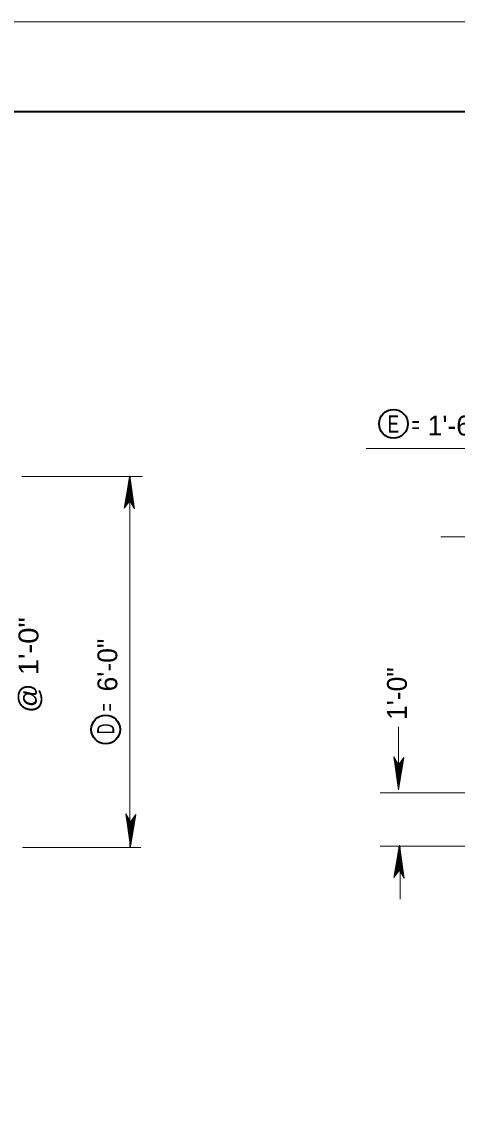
# Model space of a CAD drawing. Extents: x 144 to 252, y 360 to 425.
# Drawn here: x 182.91 to 190.1, y 407.44 to 425.48 of the extents above; entities that cross this region are included whole.
import ezdxf
from ezdxf.enums import TextEntityAlignment as Align

# ---------------------------------------------------------------- set-up
doc = ezdxf.new("R2010")
doc.units = 0
doc.header["$LTSCALE"] = 0.13
for name, color, linetype, lineweight in [('1', 7, 'Continuous', 40), ('16', 7, 'Continuous', 13), ('3', 7, 'Continuous', 13)]:
    doc.layers.add(name, color=color, linetype=linetype, lineweight=lineweight)

msp = doc.modelspace()

# ---------------------------------------------------------------- linework, layer by layer
at = {"layer": '1', "lineweight": 13}
for p, q in [((143.8112, 425.4823), (251.8112, 425.4823)), ((184.8992, 417.9522), (182.9077, 417.9522)), ((184.6937, 411.8193), (184.6937, 417.9637)), ((184.8741, 411.8077), (182.9199, 411.8077))]:
    msp.add_line(p, q, dxfattribs=at)
at = {"layer": '1'}
msp.add_lwpolyline([(250.3172, 361.9183), (250.3172, 423.9913), (149.8112, 423.9913), (149.8112, 361.9183), (230.3642, 361.9183)], dxfattribs=at)
at = {"layer": '1', "lineweight": 35}
for centre in [(189.0504, 418.8253), (184.2933, 413.7643)]:
    msp.add_circle(centre, 0.238, dxfattribs=at)
at = {"layer": '3'}
for p, q in [((190.811, 418.4168), (188.6002, 418.4168)), ((184.6897, 417.9665), (184.6004, 417.4288)), ((184.689, 417.9521), (184.6027, 417.4321)), ((184.7639, 417.4237), (184.689, 417.9521)), ((184.6897, 417.5511), (184.6897, 417.9665)), ((184.7674, 417.4178), (184.6897, 417.9665)), ((184.689, 417.9412), (184.6051, 417.4353)), ((184.689, 417.9268), (184.6082, 417.4396)), ((184.689, 417.9141), (184.6109, 417.4433)), ((184.689, 417.9027), (184.6133, 417.4467)), ((184.689, 417.8883), (184.6165, 417.4509)), ((184.689, 417.8756), (184.6192, 417.4547)), ((184.689, 417.8618), (184.6222, 417.4588)), ((184.689, 417.848), (184.6252, 417.4628)), ((184.689, 417.8347), (184.628, 417.4667)), ((184.689, 417.8208), (184.631, 417.4708)), ((184.689, 417.8082), (184.6337, 417.4746)), ((184.689, 417.7968), (184.6362, 417.478)), ((184.689, 417.7812), (184.6395, 417.4826)), ((184.7619, 417.4272), (184.689, 417.9412)), ((184.7592, 417.4318), (184.689, 417.9268)), ((184.7568, 417.4359), (184.689, 417.9141)), ((184.7568, 417.4359), (184.689, 417.9141)), ((184.7547, 417.4396), (184.689, 417.9027)), ((184.752, 417.4442), (184.689, 417.8883)), ((184.7496, 417.4482), (184.689, 417.8756)), ((184.7471, 417.4527), (184.689, 417.8618)), ((184.7445, 417.4571), (184.689, 417.848)), ((184.742, 417.4613), (184.689, 417.8347)), ((184.7393, 417.4658), (184.689, 417.8208)), ((184.7371, 417.4698), (184.689, 417.8082)), ((184.7348, 417.4736), (184.689, 417.7968)), ((184.732, 417.4786), (184.689, 417.7812)), ((184.689, 417.7673), (184.6425, 417.4867)), ((184.6885, 417.7493), (184.6456, 417.4909)), ((184.6885, 417.7354), (184.6486, 417.4951)), ((184.6885, 417.7222), (184.6514, 417.4989)), ((184.689, 417.7132), (184.6542, 417.5027)), ((184.689, 417.7012), (184.6567, 417.5062)), ((184.689, 417.6873), (184.6598, 417.5103)), ((184.689, 417.6717), (184.663, 417.515)), ((184.689, 417.6591), (184.6658, 417.5187)), ((184.689, 417.6458), (184.6686, 417.5226)), ((184.689, 417.6338), (184.6712, 417.5262)), ((184.689, 417.6193), (184.6743, 417.5304)), ((184.689, 417.6055), (184.6772, 417.5346)), ((184.689, 417.5928), (184.68, 417.5383)), ((184.7252, 417.4902), (184.6885, 417.7493)), ((184.7226, 417.4946), (184.6885, 417.7354)), ((184.7201, 417.4988), (184.6885, 417.7222)), ((184.7293, 417.483), (184.689, 417.7673)), ((184.7192, 417.5003), (184.689, 417.7132)), ((184.717, 417.5043), (184.689, 417.7012)), ((184.7143, 417.5087), (184.689, 417.6873)), ((184.7115, 417.5137), (184.689, 417.6717)), ((184.7091, 417.5177), (184.689, 417.6591)), ((184.7066, 417.522), (184.689, 417.6458)), ((184.7043, 417.5258), (184.689, 417.6338)), ((184.7017, 417.5305), (184.689, 417.6193)), ((184.6991, 417.5349), (184.689, 417.6055)), ((184.6967, 417.539), (184.689, 417.5928)), ((184.7271, 417.487), (184.6901, 417.7477)), ((184.6004, 417.4288), (184.6895, 417.5513)), ((184.689, 417.5796), (184.6828, 417.5422)), ((184.689, 417.5682), (184.6852, 417.5456)), ((184.689, 417.558), (184.6875, 417.5486)), ((184.6921, 417.5469), (184.689, 417.5682)), ((184.6895, 417.5513), (184.7674, 417.4178)), ((184.6937, 417.5442), (184.6901, 417.5693)), ((189.8336, 416.9534), (191.0873, 416.9534)), ((189.1317, 413.8104), (189.1317, 412.9573)), ((189.055, 413.3126), (189.1327, 412.7638)), ((189.1329, 413.179), (189.055, 413.3126)), ((189.0585, 413.3066), (189.1334, 412.7783)), ((189.0605, 413.3031), (189.1334, 412.7891)), ((189.0632, 413.2985), (189.1334, 412.8035)), ((189.0656, 413.2944), (189.1334, 412.8162)), ((189.0656, 413.2944), (189.1334, 412.8162)), ((189.0677, 413.2908), (189.1334, 412.8276)), ((189.0704, 413.2862), (189.1334, 412.842)), ((189.0728, 413.2821), (189.1334, 412.8547)), ((189.0753, 413.2777), (189.1334, 412.8685)), ((189.0779, 413.2732), (189.1334, 412.8823)), ((189.0804, 413.269), (189.1334, 412.8956)), ((189.0831, 413.2645), (189.1334, 412.9095)), ((189.1327, 412.7638), (189.222, 413.3015)), ((189.222, 413.3015), (189.1329, 413.179)), ((189.1334, 412.7783), (189.2197, 413.2982)), ((189.1334, 412.7891), (189.2173, 413.295)), ((189.1334, 412.8035), (189.2142, 413.2908)), ((189.1334, 412.8162), (189.2115, 413.287)), ((189.1334, 412.8276), (189.2091, 413.2837)), ((189.1334, 412.842), (189.2059, 413.2794)), ((189.1334, 412.8547), (189.2032, 413.2757)), ((189.1334, 412.8685), (189.2002, 413.2716)), ((189.1334, 412.8823), (189.1972, 413.2675)), ((189.1334, 412.8956), (189.1944, 413.2636)), ((189.0853, 413.2605), (189.1334, 412.9221)), ((189.0876, 413.2568), (189.1334, 412.9335)), ((189.0904, 413.2517), (189.1334, 412.9492)), ((189.0931, 413.2473), (189.1334, 412.963)), ((189.0953, 413.2433), (189.1323, 412.9826)), ((189.0973, 413.2402), (189.1339, 412.981)), ((189.0998, 413.2357), (189.1339, 412.9949)), ((189.1023, 413.2315), (189.1339, 413.0081)), ((189.1032, 413.23), (189.1334, 413.0172)), ((189.1054, 413.2261), (189.1334, 413.0292)), ((189.1081, 413.2217), (189.1334, 413.043)), ((189.1109, 413.2167), (189.1334, 413.0587)), ((189.1133, 413.2126), (189.1334, 413.0712)), ((189.1158, 413.2083), (189.1334, 413.0845)), ((189.1181, 413.2045), (189.1334, 413.0965)), ((189.1207, 413.1998), (189.1334, 413.111)), ((189.1233, 413.1954), (189.1334, 413.1248)), ((189.1257, 413.1913), (189.1334, 413.1375)), ((189.1287, 413.1861), (189.1323, 413.161)), ((189.1303, 413.1834), (189.1334, 413.1622)), ((189.1327, 413.1792), (189.1327, 412.7638)), ((189.1334, 412.9095), (189.1914, 413.2595)), ((189.1334, 412.9221), (189.1887, 413.2557)), ((189.1334, 412.9335), (189.1863, 413.2523)), ((189.1334, 412.9492), (189.1829, 413.2477)), ((189.1334, 412.963), (189.1799, 413.2437)), ((189.1334, 413.0172), (189.1683, 413.2277)), ((189.1334, 413.0292), (189.1657, 413.2241)), ((189.1334, 413.043), (189.1627, 413.22)), ((189.1334, 413.0587), (189.1594, 413.2153)), ((189.1334, 413.0712), (189.1567, 413.2117)), ((189.1334, 413.0845), (189.1538, 413.2077)), ((189.1334, 413.0965), (189.1512, 413.2042)), ((189.1334, 413.111), (189.1482, 413.1999)), ((189.1334, 413.1248), (189.1452, 413.1957)), ((189.1334, 413.1375), (189.1424, 413.1921)), ((189.1334, 413.1507), (189.1396, 413.1882)), ((189.1334, 413.1622), (189.1372, 413.1848)), ((189.1334, 413.1723), (189.1349, 413.1817)), ((189.1339, 412.981), (189.1768, 413.2394)), ((189.1339, 412.9949), (189.1738, 413.2353)), ((189.1339, 413.0081), (189.171, 413.2314)), ((191.9288, 412.7168), (188.8299, 412.7168)), ((184.625, 412.3703), (184.7027, 411.8216)), ((184.7029, 412.2367), (184.625, 412.3703)), ((184.6285, 412.3643), (184.7034, 411.836)), ((184.6305, 412.3608), (184.7034, 411.8468)), ((184.6332, 412.3562), (184.7034, 411.8612)), ((184.6356, 412.3522), (184.7034, 411.874)), ((184.6356, 412.3522), (184.7034, 411.874)), ((184.6377, 412.3485), (184.7034, 411.8853)), ((184.6404, 412.3439), (184.7034, 411.8997)), ((184.6428, 412.3398), (184.7034, 411.9125)), ((184.6453, 412.3354), (184.7034, 411.9262)), ((184.6479, 412.331), (184.7034, 411.9401)), ((184.6504, 412.3268), (184.7034, 411.9533)), ((184.6531, 412.3222), (184.7034, 411.9672)), ((184.6553, 412.3182), (184.7034, 411.9798)), ((184.6576, 412.3145), (184.7034, 411.9912)), ((184.6604, 412.3095), (184.7034, 412.0069)), ((184.6631, 412.3051), (184.7034, 412.0207)), ((184.6653, 412.3011), (184.7023, 412.0403)), ((184.6672, 412.2979), (184.7039, 412.0387)), ((184.6698, 412.2935), (184.7039, 412.0527)), ((184.6723, 412.2892), (184.7039, 412.0658)), ((184.6732, 412.2877), (184.7034, 412.0749)), ((184.6754, 412.2838), (184.7034, 412.0869)), ((184.6781, 412.2794), (184.7034, 412.1008)), ((184.6809, 412.2744), (184.7034, 412.1164)), ((184.6833, 412.2703), (184.7034, 412.129)), ((184.6858, 412.2661), (184.7034, 412.1422)), ((184.6881, 412.2622), (184.7034, 412.1542)), ((184.6907, 412.2576), (184.7034, 412.1687)), ((184.6933, 412.2532), (184.7034, 412.1826)), ((184.6957, 412.2491), (184.7034, 412.1952)), ((184.6987, 412.2438), (184.7023, 412.2188)), ((184.7003, 412.2412), (184.7034, 412.2199)), ((184.7027, 411.8216), (184.792, 412.3592)), ((184.7027, 412.237), (184.7027, 411.8216)), ((184.792, 412.3592), (184.7029, 412.2367)), ((184.7034, 411.836), (184.7897, 412.356)), ((184.7034, 411.8468), (184.7873, 412.3528)), ((184.7034, 411.8612), (184.7842, 412.3485)), ((184.7034, 411.874), (184.7815, 412.3447)), ((184.7034, 411.8853), (184.7791, 412.3414)), ((184.7034, 411.8997), (184.7759, 412.3372)), ((184.7034, 411.9125), (184.7732, 412.3334)), ((184.7034, 411.9262), (184.7703, 412.3293)), ((184.7034, 411.9401), (184.7672, 412.3252)), ((184.7034, 411.9533), (184.7644, 412.3213)), ((184.7034, 411.9672), (184.7614, 412.3173)), ((184.7034, 411.9798), (184.7587, 412.3135)), ((184.7034, 411.9912), (184.7562, 412.3101)), ((184.7034, 412.0069), (184.7529, 412.3055)), ((184.7034, 412.0207), (184.7499, 412.3014)), ((184.7034, 412.0749), (184.7382, 412.2854)), ((184.7034, 412.0869), (184.7357, 412.2818)), ((184.7034, 412.1008), (184.7327, 412.2777)), ((184.7034, 412.1164), (184.7294, 412.2731)), ((184.7034, 412.129), (184.7267, 412.2694)), ((184.7034, 412.1422), (184.7238, 412.2655)), ((184.7034, 412.1542), (184.7212, 412.2619)), ((184.7034, 412.1687), (184.7182, 412.2577)), ((184.7034, 412.1826), (184.7152, 412.2535)), ((184.7034, 412.1952), (184.7124, 412.2498)), ((184.7034, 412.2085), (184.7096, 412.2459)), ((184.7034, 412.2199), (184.7072, 412.2425)), ((184.7034, 412.2301), (184.7049, 412.2395)), ((184.7039, 412.0387), (184.7468, 412.2972)), ((184.7039, 412.0527), (184.7438, 412.293)), ((184.7039, 412.0658), (184.741, 412.2892)), ((190.6728, 411.8347), (188.8299, 411.8347)), ((189.1485, 411.851), (189.0592, 411.3133)), ((189.1478, 411.8366), (189.0616, 411.3166)), ((189.1478, 411.8257), (189.0639, 411.3198)), ((189.2227, 411.3082), (189.1478, 411.8366)), ((189.2207, 411.3117), (189.1478, 411.8257)), ((189.1485, 411.4356), (189.1485, 411.851)), ((189.2262, 411.3022), (189.1485, 411.851)), ((189.1478, 411.8113), (189.0671, 411.3241)), ((189.1478, 411.7986), (189.0697, 411.3278)), ((189.1478, 411.7872), (189.0722, 411.3312)), ((189.1478, 411.7728), (189.0753, 411.3354)), ((189.1478, 411.7601), (189.0781, 411.3392)), ((189.1478, 411.7463), (189.081, 411.3433)), ((189.1478, 411.7325), (189.084, 411.3473)), ((189.1478, 411.7192), (189.0868, 411.3512)), ((189.1478, 411.7053), (189.0898, 411.3553)), ((189.1478, 411.6927), (189.0925, 411.3591)), ((189.1478, 411.6813), (189.095, 411.3625)), ((189.1478, 411.6657), (189.0983, 411.3671)), ((189.1478, 411.6518), (189.1013, 411.3712)), ((189.2181, 411.3163), (189.1478, 411.8113)), ((189.2157, 411.3204), (189.1478, 411.7986)), ((189.2157, 411.3204), (189.1478, 411.7986)), ((189.2135, 411.3241), (189.1478, 411.7872)), ((189.2108, 411.3287), (189.1478, 411.7728)), ((189.2084, 411.3327), (189.1478, 411.7601)), ((189.2059, 411.3372), (189.1478, 411.7463)), ((189.2033, 411.3416), (189.1478, 411.7325)), ((189.2008, 411.3458), (189.1478, 411.7192)), ((189.1982, 411.3503), (189.1478, 411.7053)), ((189.1959, 411.3543), (189.1478, 411.6927)), ((189.1937, 411.3581), (189.1478, 411.6813)), ((189.1908, 411.3631), (189.1478, 411.6657)), ((189.1882, 411.3675), (189.1478, 411.6518)), ((189.159, 411.8099), (189.159, 410.9568)), ((189.1473, 411.6338), (189.1044, 411.3754)), ((189.1473, 411.6199), (189.1074, 411.3796)), ((189.1473, 411.6067), (189.1103, 411.3834)), ((189.1478, 411.5977), (189.113, 411.3872)), ((189.1478, 411.5857), (189.1156, 411.3907)), ((189.1478, 411.5718), (189.1186, 411.3948)), ((189.1478, 411.5562), (189.1218, 411.3995)), ((189.1478, 411.5436), (189.1246, 411.4032)), ((189.1478, 411.5303), (189.1274, 411.4071)), ((189.1478, 411.5183), (189.1301, 411.4107)), ((189.1478, 411.5038), (189.1331, 411.4149)), ((189.1478, 411.49), (189.1361, 411.4191)), ((189.1478, 411.4773), (189.1388, 411.4228)), ((189.1478, 411.4641), (189.1417, 411.4267)), ((189.184, 411.3747), (189.1473, 411.6338)), ((189.1814, 411.3791), (189.1473, 411.6199)), ((189.1789, 411.3833), (189.1473, 411.6067)), ((189.1781, 411.3848), (189.1478, 411.5977)), ((189.1758, 411.3887), (189.1478, 411.5857)), ((189.1732, 411.3932), (189.1478, 411.5718)), ((189.1703, 411.3982), (189.1478, 411.5562)), ((189.1679, 411.4022), (189.1478, 411.5436)), ((189.1654, 411.4065), (189.1478, 411.5303)), ((189.1632, 411.4103), (189.1478, 411.5183)), ((189.1605, 411.415), (189.1478, 411.5038)), ((189.1579, 411.4194), (189.1478, 411.49)), ((189.1556, 411.4235), (189.1478, 411.4773)), ((189.1859, 411.3715), (189.1489, 411.6322)), ((189.0592, 411.3133), (189.1483, 411.4358)), ((189.1478, 411.4527), (189.1441, 411.4301)), ((189.1478, 411.4425), (189.1463, 411.4331)), ((189.1509, 411.4314), (189.1478, 411.4527)), ((189.1483, 411.4358), (189.2262, 411.3022)), ((189.1525, 411.4287), (189.1489, 411.4538))]:
    msp.add_line(p, q, dxfattribs=at)

# ---------------------------------------------------------------- texts
at = {"layer": '1'}
for s, width, p in [('E', 0.75, (189.0479, 418.6809)), ('=', 0.6, (189.4159, 418.668))]:
    msp.add_text(s, height=0.2833, dxfattribs=dict(at, width=width)).set_placement(p, align=Align.CENTER)
for s, width, p in [('=', 0.6, (184.4506, 414.1298)), ('D', 0.65, (184.4352, 413.773))]:
    msp.add_text(s, height=0.2833, rotation=90, dxfattribs=dict(at, width=width)).set_placement(p, align=Align.CENTER)
at = {"layer": '16'}
msp.add_text('1\'-6"', height=0.3281, dxfattribs=at).set_placement((190.0525, 418.6325), align=Align.CENTER)
at = {"layer": '16', "width": 1.1}
msp.add_text('@ 1\'-0"', height=0.3281, rotation=90, dxfattribs=at).set_placement((183.1803, 414.8309), align=Align.CENTER)
at = {"layer": '16'}
msp.add_text('6\'-0"', height=0.3281, rotation=90, dxfattribs=at).set_placement((184.4847, 414.831), align=Align.CENTER)
msp.add_text('1\'-0"', height=0.3281, rotation=90, dxfattribs=at).set_placement((189.2726, 413.9211))

doc.saveas('drawing.dxf')
